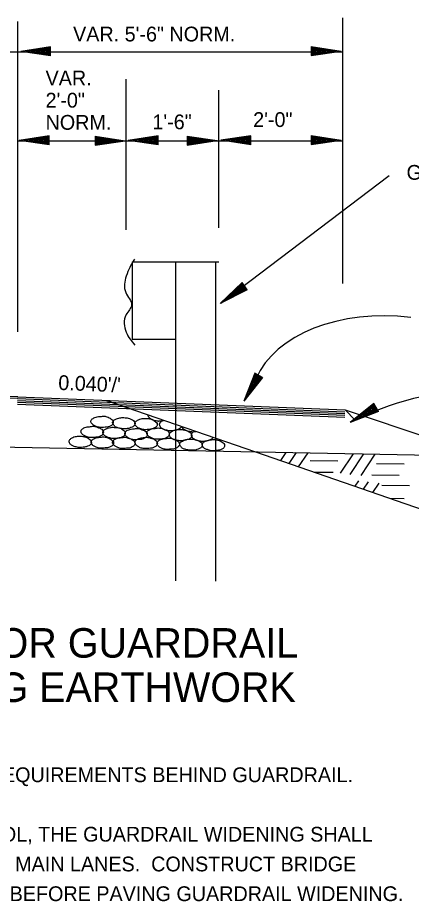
# Model space of a CAD drawing. Extents: x 1929624 to 1936506, y 596315 to 605721.
# Drawn here: x 1934004.9 to 1934166.9, y 603935.3 to 604298.6 of the extents above; entities that cross this region are included whole.
import ezdxf

# ---------------------------------------------------------------- set-up
doc = ezdxf.new("R2010")
doc.units = 0
doc.layers.add('Default', color=7, linetype='Continuous')
doc.layers.add('R_Border', color=7, linetype='Continuous')

msp = doc.modelspace()

# ---------------------------------------------------------------- linework, layer by layer
at = {"layer": 'Default'}
for p, q in [((1934138.62, 604189.31), (1934138.62, 604298.55)), ((1934004.92, 604169.42), (1934004.92, 604296.97)), ((1934018.45, 604286.54), (1934006.13, 604284.69)), ((1934018.45, 604286.22), (1934008.19, 604284.69)), ((1934018.45, 604282.82), (1934018.45, 604286.54)), ((1934125.68, 604286.66), (1934138, 604284.79)), ((1934125.68, 604286.66), (1934125.68, 604282.94)), ((1934125.68, 604286.34), (1934135.94, 604284.79)), ((1933808.09, 604284.47), (1934138.62, 604284.47)), ((1934018.45, 604282.82), (1934006.13, 604284.69)), ((1934018.45, 604283.14), (1934008.19, 604284.69)), ((1934018.45, 604285.9), (1934010.31, 604284.69)), ((1934018.45, 604283.46), (1934010.31, 604284.69)), ((1934018.45, 604285.6), (1934012.38, 604284.69)), ((1934018.45, 604283.76), (1934012.38, 604284.69)), ((1934018.45, 604285.28), (1934014.44, 604284.69)), ((1934018.45, 604284.07), (1934014.44, 604284.69)), ((1934018.45, 604284.96), (1934016.51, 604284.69)), ((1934018.45, 604284.39), (1934016.51, 604284.69)), ((1934125.68, 604286.02), (1934133.82, 604284.79)), ((1934125.68, 604285.72), (1934131.75, 604284.79)), ((1934125.68, 604285.4), (1934129.69, 604284.79)), ((1934125.68, 604285.08), (1934127.62, 604284.79)), ((1934125.68, 604282.94), (1934138, 604284.79)), ((1934125.68, 604284.2), (1934129.69, 604284.79)), ((1934125.68, 604283.58), (1934133.82, 604284.79)), ((1934125.68, 604283.26), (1934135.94, 604284.79)), ((1934125.68, 604283.88), (1934131.75, 604284.79)), ((1934125.68, 604284.52), (1934127.62, 604284.79)), ((1934049.48, 604211.4), (1934049.48, 604273.27)), ((1934087.69, 604212.21), (1934087.69, 604268.77)), ((1934017.79, 604249.97), (1934005.46, 604248.13)), ((1934017.79, 604246.26), (1934017.79, 604249.97)), ((1934036.81, 604249.85), (1934049.14, 604247.98)), ((1934036.81, 604249.85), (1934036.81, 604246.14)), ((1934062.69, 604249.97), (1934050.37, 604248.13)), ((1934062.69, 604246.26), (1934062.69, 604249.97)), ((1934074.67, 604249.88), (1934087, 604248.01)), ((1934074.67, 604249.88), (1934074.67, 604246.16)), ((1934100.78, 604250), (1934088.45, 604248.15)), ((1934100.78, 604246.28), (1934100.78, 604250)), ((1934125.68, 604250.07), (1934138, 604248.2)), ((1934125.68, 604250.07), (1934125.68, 604246.36)), ((1934004.92, 604247.91), (1934138.62, 604247.91)), ((1934017.79, 604246.26), (1934005.46, 604248.13)), ((1934017.79, 604249.65), (1934007.53, 604248.13)), ((1934017.79, 604246.58), (1934007.53, 604248.13)), ((1934017.79, 604249.33), (1934009.65, 604248.13)), ((1934017.79, 604246.9), (1934009.65, 604248.13)), ((1934017.79, 604249.04), (1934011.71, 604248.13)), ((1934017.79, 604247.19), (1934011.71, 604248.13)), ((1934017.79, 604248.72), (1934013.78, 604248.13)), ((1934017.79, 604247.51), (1934013.78, 604248.13)), ((1934017.79, 604248.4), (1934015.85, 604248.13)), ((1934017.79, 604247.83), (1934015.85, 604248.13)), ((1934036.81, 604249.53), (1934047.07, 604247.98)), ((1934036.81, 604249.21), (1934044.95, 604247.98)), ((1934036.81, 604248.92), (1934042.89, 604247.98)), ((1934036.81, 604248.6), (1934040.82, 604247.98)), ((1934036.81, 604248.28), (1934038.75, 604247.98)), ((1934036.81, 604246.14), (1934049.14, 604247.98)), ((1934036.81, 604247.39), (1934040.82, 604247.98)), ((1934036.81, 604246.78), (1934044.95, 604247.98)), ((1934036.81, 604246.46), (1934047.07, 604247.98)), ((1934036.81, 604247.07), (1934042.89, 604247.98)), ((1934036.81, 604247.71), (1934038.75, 604247.98)), ((1934062.69, 604246.26), (1934050.37, 604248.13)), ((1934062.69, 604249.65), (1934052.43, 604248.13)), ((1934062.69, 604246.58), (1934052.43, 604248.13)), ((1934062.69, 604249.33), (1934054.55, 604248.13)), ((1934062.69, 604246.9), (1934054.55, 604248.13)), ((1934062.69, 604249.04), (1934056.61, 604248.13)), ((1934062.69, 604247.19), (1934056.61, 604248.13)), ((1934062.69, 604248.72), (1934058.68, 604248.13)), ((1934062.69, 604247.51), (1934058.68, 604248.13)), ((1934062.69, 604248.4), (1934060.75, 604248.13)), ((1934062.69, 604247.83), (1934060.75, 604248.13)), ((1934074.67, 604249.56), (1934084.93, 604248.01)), ((1934074.67, 604249.24), (1934082.82, 604248.01)), ((1934074.67, 604248.94), (1934080.75, 604248.01)), ((1934074.67, 604248.62), (1934078.68, 604248.01)), ((1934074.67, 604248.3), (1934076.62, 604248.01)), ((1934074.67, 604246.16), (1934087, 604248.01)), ((1934074.67, 604247.42), (1934078.68, 604248.01)), ((1934074.67, 604246.8), (1934082.82, 604248.01)), ((1934074.67, 604246.48), (1934084.93, 604248.01)), ((1934074.67, 604247.1), (1934080.75, 604248.01)), ((1934074.67, 604247.74), (1934076.62, 604248.01)), ((1934100.78, 604246.28), (1934088.45, 604248.15)), ((1934100.78, 604249.68), (1934090.52, 604248.15)), ((1934100.78, 604246.6), (1934090.52, 604248.15)), ((1934100.78, 604249.36), (1934092.63, 604248.15)), ((1934100.78, 604246.92), (1934092.63, 604248.15)), ((1934100.78, 604249.06), (1934094.7, 604248.15)), ((1934100.78, 604247.22), (1934094.7, 604248.15)), ((1934100.78, 604248.74), (1934096.77, 604248.15)), ((1934100.78, 604247.54), (1934096.77, 604248.15)), ((1934100.78, 604248.42), (1934098.83, 604248.15)), ((1934100.78, 604247.86), (1934098.83, 604248.15)), ((1934125.68, 604249.75), (1934135.94, 604248.2)), ((1934125.68, 604249.43), (1934133.82, 604248.2)), ((1934125.68, 604249.14), (1934131.75, 604248.2)), ((1934125.68, 604248.82), (1934129.69, 604248.2)), ((1934125.68, 604248.5), (1934127.62, 604248.2)), ((1934125.68, 604246.36), (1934138, 604248.2)), ((1934125.68, 604247.61), (1934129.69, 604248.2)), ((1934125.68, 604247), (1934133.82, 604248.2)), ((1934125.68, 604246.68), (1934135.94, 604248.2)), ((1934125.68, 604247.29), (1934131.75, 604248.2)), ((1934125.68, 604247.93), (1934127.62, 604248.2)), ((1934088.5, 604181.23), (1934157.81, 604233.61)), ((1934052.04, 604198.23), (1934052.04, 604166.4)), ((1934052.04, 604198.23), (1934087.69, 604198.23)), ((1934069.88, 604198.23), (1934069.88, 604067.05)), ((1934086.26, 604198.08), (1934086.26, 604066.92)), ((1934097.24, 604189.65), (1934088.18, 604181.09)), ((1934097.44, 604189.41), (1934089.86, 604182.25)), ((1934097.64, 604189.11), (1934091.66, 604183.52)), ((1934097.76, 604188.86), (1934093.32, 604184.68)), ((1934097.95, 604188.65), (1934095, 604185.86)), ((1934098.12, 604188.37), (1934096.7, 604187.05)), ((1934099.34, 604186.64), (1934097.24, 604189.65)), ((1934099.34, 604186.64), (1934088.18, 604181.09)), ((1934099.19, 604186.87), (1934089.86, 604182.25)), ((1934098.97, 604187.14), (1934091.66, 604183.52)), ((1934098.79, 604187.41), (1934093.32, 604184.68)), ((1934098.6, 604187.68), (1934095, 604185.86)), ((1934098.47, 604187.96), (1934096.7, 604187.05)), ((1934052.04, 604166.4), (1934069.88, 604166.4)), ((1934102.48, 604152.47), (1934097.9, 604140.86)), ((1934102.72, 604152.27), (1934098.93, 604142.65)), ((1934103.02, 604152.12), (1934099.99, 604144.5)), ((1934103.26, 604151.98), (1934101, 604146.24)), ((1934103.56, 604151.83), (1934102.06, 604148.07)), ((1934105.67, 604150.6), (1934102.48, 604152.47)), ((1934004.92, 604142.7), (1933857.3, 604148.61)), ((1934105.67, 604150.6), (1934097.9, 604140.86)), ((1934105.43, 604150.77), (1934098.93, 604142.65)), ((1934105.11, 604150.89), (1934099.99, 604144.5)), ((1934104.86, 604151.07), (1934101, 604146.24)), ((1934104.59, 604151.21), (1934102.06, 604148.07)), ((1934103.85, 604151.66), (1934103.12, 604149.84)), ((1934104.32, 604151.39), (1934103.12, 604149.84)), ((1934004.92, 604141.96), (1933857.3, 604147.87)), ((1934004.86, 604141.23), (1934139.51, 604135.84)), ((1934004.88, 604141.96), (1934139.54, 604136.58)), ((1934004.92, 604142.7), (1934139.58, 604137.31)), ((1934041.45, 604141.24), (1934102.69, 604120.1)), ((1934004.8, 604139.75), (1934139.46, 604134.36)), ((1934004.82, 604140.49), (1934139.48, 604135.1)), ((1934139.58, 604137.31), (1934320.2, 604077.27)), ((1934139.58, 604137.31), (1934143.81, 604133.11)), ((1934151.44, 604139.95), (1934141.69, 604132.17)), ((1934151.61, 604139.65), (1934143.49, 604133.18)), ((1934151.76, 604139.38), (1934145.31, 604134.26)), ((1934152.96, 604137.26), (1934145.31, 604134.26)), ((1934151.91, 604139.13), (1934147.08, 604135.3)), ((1934152.82, 604137.51), (1934147.08, 604135.3)), ((1934152.05, 604138.84), (1934148.88, 604136.33)), ((1934152.67, 604137.78), (1934148.88, 604136.33)), ((1934152.22, 604138.57), (1934150.7, 604137.36)), ((1934152.52, 604138.08), (1934150.7, 604137.36)), ((1934153.31, 604136.72), (1934151.44, 604139.95)), ((1934153.31, 604136.72), (1934141.69, 604132.17)), ((1934153.14, 604136.99), (1934143.49, 604133.18)), ((1933803.65, 604126.05), (1934197.03, 604118.22)), ((1934102.69, 604120.1), (1934226.74, 604077.27))]:
    msp.add_line(p, q, dxfattribs=at)
msp.add_arc((1934197.2, 604023.84), 121.72, 64.8876, 117.1378, dxfattribs=at)
msp.add_ellipse((1934161.79, 604135.44), major_axis=(-60.8, 7.42), ratio=0.655798, start_param=4.712389, end_param=6.093533, dxfattribs=at)
for points in [[(1934052.9, 604199.27), (1934049.55, 604192.35), (1934049.38, 604185.61), (1934051.79, 604180.42), (1934049.55, 604176.48), (1934049.55, 604169.22), (1934053.1, 604163.98)], [(1934039.79, 604134.69), (1934038.16, 604134.59), (1934036.19, 604134), (1934035.16, 604133.07), (1934035.01, 604132.52), (1934035.5, 604131.54), (1934036.1, 604131.1), (1934037.23, 604130.56), (1934038.8, 604130.11), (1934039.64, 604130.11), (1934040.82, 604130.21), (1934042.15, 604130.36), (1934043.18, 604130.75), (1934044.07, 604131.59), (1934044.21, 604132.23), (1934043.92, 604133.11), (1934043.28, 604133.7), (1934042.59, 604134.1), (1934041.51, 604134.54), (1934040.82, 604134.69), (1934039.79, 604134.69)], [(1934048.6, 604134.16), (1934046.98, 604134.07), (1934045.06, 604133.38), (1934044.08, 604132.59), (1934043.93, 604132.05), (1934044.47, 604131.01), (1934044.91, 604130.47), (1934046.09, 604129.98), (1934047.57, 604129.64), (1934048.41, 604129.54), (1934049.64, 604129.59), (1934051.01, 604129.83), (1934052, 604130.28), (1934053.03, 604131.06), (1934053.18, 604131.7), (1934052.88, 604132.59), (1934052.15, 604133.23), (1934051.41, 604133.57), (1934050.32, 604133.92), (1934049.64, 604134.07), (1934048.6, 604134.16)], [(1934057.78, 604133.8), (1934056.16, 604133.75), (1934054.19, 604133.06), (1934053.2, 604132.17), (1934053.06, 604131.58), (1934053.6, 604130.6), (1934054.14, 604130.15), (1934055.22, 604129.66), (1934056.8, 604129.22), (1934057.63, 604129.17), (1934058.81, 604129.27), (1934060.14, 604129.51), (1934061.17, 604129.91), (1934062.16, 604130.7), (1934062.31, 604131.29), (1934062.01, 604132.17), (1934061.27, 604132.76), (1934060.58, 604133.25), (1934059.5, 604133.6), (1934058.81, 604133.75), (1934057.78, 604133.8)], [(1934058.4, 604135.39), (1934058.4, 604135.36), (1934058.4, 604135.29), (1934058.4, 604135.22), (1934058.48, 604134.95), (1934058.59, 604134.69), (1934058.75, 604134.43), (1934058.84, 604134.31), (1934058.94, 604134.19), (1934059.2, 604133.94), (1934059.49, 604133.75), (1934059.75, 604133.6), (1934060.02, 604133.47), (1934060.29, 604133.35), (1934060.57, 604133.25), (1934061.35, 604133.03), (1934062.14, 604132.86), (1934062.56, 604132.79), (1934062.77, 604132.77), (1934062.98, 604132.76), (1934063.57, 604132.79), (1934063.87, 604132.82), (1934064.16, 604132.86), (1934064.68, 604132.94), (1934065.2, 604133.04)], [(1934035.71, 604130.58), (1934033.99, 604130.38), (1934032.07, 604129.89), (1934031.08, 604128.96), (1934030.94, 604128.42), (1934031.43, 604127.38), (1934032.02, 604126.94), (1934033.1, 604126.35), (1934034.68, 604125.95), (1934035.46, 604125.95), (1934036.69, 604126.05), (1934038.07, 604126.15), (1934039.11, 604126.64), (1934039.99, 604127.48), (1934040.14, 604128.12), (1934039.84, 604129.01), (1934039.11, 604129.6), (1934038.42, 604129.89), (1934037.33, 604130.33), (1934036.69, 604130.53), (1934035.71, 604130.58)], [(1934044.64, 604130.16), (1934043.02, 604130.11), (1934041.05, 604129.47), (1934040.06, 604128.54), (1934039.92, 604128), (1934040.46, 604126.96), (1934041, 604126.52), (1934042.08, 604126.03), (1934043.66, 604125.63), (1934044.49, 604125.54), (1934045.67, 604125.63), (1934047, 604125.88), (1934048.04, 604126.27), (1934049.02, 604127.06), (1934049.17, 604127.7), (1934048.87, 604128.59), (1934048.13, 604129.18), (1934047.45, 604129.62), (1934046.36, 604129.97), (1934045.67, 604130.11), (1934044.64, 604130.16)], [(1934065.06, 604133.09), (1934064.76, 604132.97), (1934064.52, 604132.86), (1934064.28, 604132.74), (1934063.98, 604132.55), (1934063.73, 604132.34), (1934063.5, 604132.09), (1934063.4, 604131.95), (1934063.29, 604131.8), (1934063.22, 604131.67), (1934063.16, 604131.53), (1934063.14, 604131.39), (1934063.14, 604131.33), (1934063.15, 604131.26), (1934063.22, 604130.99), (1934063.34, 604130.73), (1934063.49, 604130.47), (1934063.58, 604130.35), (1934063.69, 604130.23), (1934063.94, 604129.98), (1934064.23, 604129.78), (1934064.49, 604129.64), (1934064.76, 604129.51), (1934065.03, 604129.39), (1934065.31, 604129.29), (1934066.09, 604129.07), (1934066.88, 604128.9), (1934067.72, 604128.8), (1934067.87, 604128.8), (1934068.02, 604128.81), (1934068.31, 604128.83), (1934068.9, 604128.9), (1934069.24, 604128.95), (1934069.57, 604129.01), (1934069.9, 604129.07), (1934070.23, 604129.14), (1934070.5, 604129.22), (1934070.76, 604129.31), (1934071.01, 604129.42), (1934071.26, 604129.54), (1934071.54, 604129.68), (1934071.8, 604129.85), (1934072.03, 604130.06), (1934072.14, 604130.19), (1934072.25, 604130.33), (1934072.32, 604130.45), (1934072.36, 604130.57)], [(1934072.31, 604130.59), (1934072.4, 604130.38), (1934072.5, 604130.18), (1934072.64, 604129.99), (1934072.79, 604129.8), (1934073.04, 604129.55), (1934073.33, 604129.36), (1934073.59, 604129.21), (1934073.86, 604129.08), (1934074.13, 604128.97), (1934074.41, 604128.87), (1934075.19, 604128.64), (1934075.99, 604128.47), (1934076.4, 604128.4), (1934076.61, 604128.38), (1934076.82, 604128.37), (1934077.41, 604128.4), (1934078, 604128.47), (1934078.31, 604128.52)], [(1934030.69, 604126.49), (1934029.07, 604126.44), (1934027.1, 604125.75), (1934026.16, 604124.86), (1934026.02, 604124.27), (1934026.51, 604123.29), (1934027.1, 604122.85), (1934028.13, 604122.35), (1934029.76, 604121.91), (1934030.54, 604121.86), (1934031.77, 604121.96), (1934033.1, 604122.21), (1934034.14, 604122.6), (1934035.07, 604123.39), (1934035.22, 604123.98), (1934034.92, 604124.86), (1934034.18, 604125.45), (1934033.5, 604125.95), (1934032.41, 604126.29), (1934031.72, 604126.44), (1934030.69, 604126.49)], [(1934053.74, 604129.66), (1934052.11, 604129.51), (1934050.14, 604128.97), (1934049.11, 604128.04), (1934048.96, 604127.5), (1934049.5, 604126.51), (1934050.05, 604126.07), (1934051.18, 604125.43), (1934052.7, 604125.09), (1934053.54, 604125.09), (1934054.72, 604125.18), (1934056.15, 604125.23), (1934057.13, 604125.73), (1934058.07, 604126.56), (1934058.21, 604127.2), (1934057.92, 604128.09), (1934057.23, 604128.68), (1934056.49, 604129.02), (1934055.46, 604129.37), (1934054.77, 604129.66), (1934053.74, 604129.66)], [(1934062.69, 604129.89), (1934061.07, 604129.69), (1934059.15, 604129.2), (1934058.16, 604128.27), (1934058.02, 604127.73), (1934058.56, 604126.69), (1934059.1, 604126.25), (1934060.18, 604125.66), (1934061.76, 604125.27), (1934062.54, 604125.27), (1934063.77, 604125.36), (1934065.1, 604125.46), (1934066.19, 604125.95), (1934067.12, 604126.79), (1934067.27, 604127.43), (1934066.97, 604128.32), (1934066.23, 604128.91), (1934065.5, 604129.2), (1934064.46, 604129.69), (1934063.73, 604129.84), (1934062.69, 604129.89)], [(1934071.99, 604129.25), (1934070.37, 604129.2), (1934068.4, 604128.56), (1934067.42, 604127.63), (1934067.27, 604127.09), (1934067.81, 604126.05), (1934068.35, 604125.61), (1934069.43, 604125.12), (1934071.01, 604124.72), (1934071.84, 604124.63), (1934073.03, 604124.72), (1934074.35, 604124.97), (1934075.39, 604125.36), (1934076.37, 604126.15), (1934076.52, 604126.79), (1934076.22, 604127.68), (1934075.49, 604128.27), (1934074.8, 604128.71), (1934073.71, 604129.05), (1934073.03, 604129.2), (1934071.99, 604129.25)], [(1934077.89, 604128.66), (1934077.63, 604128.54), (1934077.49, 604128.47), (1934077.36, 604128.41), (1934077.07, 604128.22), (1934076.82, 604128.01), (1934076.59, 604127.76), (1934076.48, 604127.62), (1934076.38, 604127.47), (1934076.3, 604127.34), (1934076.25, 604127.2), (1934076.22, 604127.06), (1934076.22, 604127), (1934076.23, 604126.93), (1934076.3, 604126.66), (1934076.42, 604126.4), (1934076.58, 604126.14), (1934076.67, 604126.02), (1934076.77, 604125.9), (1934077.03, 604125.65), (1934077.31, 604125.45), (1934077.58, 604125.31), (1934077.84, 604125.18), (1934078.12, 604125.06), (1934078.4, 604124.96), (1934079.18, 604124.74), (1934079.97, 604124.57), (1934080.81, 604124.47), (1934080.96, 604124.47), (1934081.1, 604124.48), (1934081.4, 604124.5), (1934081.99, 604124.57), (1934082.32, 604124.62), (1934082.66, 604124.67), (1934082.99, 604124.74), (1934083.32, 604124.81), (1934083.58, 604124.89), (1934083.84, 604124.98), (1934084.1, 604125.09), (1934084.35, 604125.21), (1934084.63, 604125.35), (1934084.88, 604125.52), (1934085.12, 604125.73), (1934085.23, 604125.85), (1934085.28, 604125.92), (1934085.33, 604125.99), (1934085.38, 604126.07)], [(1934039.79, 604126.2), (1934038.17, 604126.05), (1934036.2, 604125.46), (1934035.27, 604124.58), (1934035.12, 604123.99), (1934035.61, 604123), (1934036.1, 604122.56), (1934037.24, 604122.07), (1934038.76, 604121.58), (1934039.6, 604121.58), (1934040.83, 604121.67), (1934042.21, 604121.87), (1934043.19, 604122.22), (1934044.17, 604123.1), (1934044.32, 604123.69), (1934044.03, 604124.58), (1934043.29, 604125.17), (1934042.55, 604125.61), (1934041.52, 604126), (1934040.83, 604126.15), (1934039.79, 604126.2)], [(1934048.64, 604126.07), (1934047.02, 604125.87), (1934045.05, 604125.33), (1934044.07, 604124.45), (1934043.92, 604123.86), (1934044.46, 604122.87), (1934045, 604122.43), (1934046.08, 604121.84), (1934047.61, 604121.44), (1934048.45, 604121.44), (1934049.68, 604121.54), (1934051.01, 604121.64), (1934052.04, 604122.08), (1934053.02, 604122.97), (1934053.17, 604123.56), (1934052.87, 604124.45), (1934052.14, 604125.04), (1934051.4, 604125.38), (1934050.32, 604125.77), (1934049.68, 604126.02), (1934048.64, 604126.07)], [(1934057.9, 604126.08), (1934056.23, 604125.88), (1934054.26, 604125.34), (1934053.28, 604124.45), (1934053.13, 604123.86), (1934053.67, 604122.88), (1934054.21, 604122.44), (1934055.34, 604121.8), (1934056.87, 604121.45), (1934057.66, 604121.45), (1934058.89, 604121.5), (1934060.26, 604121.65), (1934061.3, 604122.09), (1934062.23, 604122.98), (1934062.38, 604123.57), (1934062.08, 604124.45), (1934061.35, 604125.04), (1934060.61, 604125.39), (1934059.58, 604125.73), (1934058.94, 604125.93), (1934057.9, 604126.08)], [(1934066.97, 604125.71), (1934065.25, 604125.51), (1934063.38, 604125.02), (1934062.35, 604124.08), (1934062.2, 604123.54), (1934062.74, 604122.51), (1934063.28, 604122.07), (1934064.41, 604121.48), (1934065.94, 604121.08), (1934066.73, 604121.08), (1934067.96, 604121.18), (1934069.38, 604121.28), (1934070.37, 604121.77), (1934071.3, 604122.61), (1934071.45, 604123.25), (1934071.16, 604124.13), (1934070.42, 604124.72), (1934069.73, 604125.02), (1934068.65, 604125.41), (1934068.01, 604125.66), (1934066.97, 604125.71)], [(1934076.25, 604125.33), (1934074.62, 604125.23), (1934072.71, 604124.54), (1934071.72, 604123.76), (1934071.57, 604123.22), (1934072.12, 604122.18), (1934072.56, 604121.64), (1934073.74, 604121.15), (1934075.22, 604120.8), (1934076.05, 604120.71), (1934077.28, 604120.76), (1934078.66, 604121), (1934079.64, 604121.44), (1934080.68, 604122.23), (1934080.82, 604122.87), (1934080.53, 604123.76), (1934079.79, 604124.4), (1934079.05, 604124.74), (1934077.97, 604125.09), (1934077.28, 604125.23), (1934076.25, 604125.33)], [(1934085.5, 604125.14), (1934083.88, 604125), (1934081.91, 604124.4), (1934080.97, 604123.52), (1934080.82, 604122.93), (1934081.32, 604121.94), (1934081.81, 604121.5), (1934082.94, 604121.01), (1934084.47, 604120.52), (1934085.3, 604120.52), (1934086.53, 604120.62), (1934087.91, 604120.81), (1934088.89, 604121.16), (1934089.88, 604122.04), (1934090.03, 604122.63), (1934089.73, 604123.52), (1934088.99, 604124.11), (1934088.26, 604124.55), (1934087.22, 604124.95), (1934086.53, 604125.09), (1934085.5, 604125.14)]]:
    msp.add_spline(points, degree=3, dxfattribs=at)
at = {"layer": 'R_Border'}
for p, q in [((1934113.15, 604116.49), (1934115.42, 604119.84)), ((1934116.64, 604115.28), (1934119.66, 604119.76)), ((1934120.5, 604113.95), (1934124.36, 604119.67)), ((1934137.73, 604111.31), (1934143.11, 604119.29)), ((1934141.71, 604110.84), (1934147.36, 604119.21)), ((1934146.16, 604110.38), (1934152.05, 604119.12)), ((1934125.3, 604116.5), (1934136.61, 604116.41)), ((1934152.56, 604115.3), (1934163.87, 604115.2)), ((1934126.89, 604111.74), (1934134.67, 604111.68)), ((1934143.72, 604105.93), (1934145.23, 604108.18)), ((1934150.61, 604110.57), (1934161.92, 604110.47)), ((1934147.21, 604104.73), (1934149.22, 604107.71)), ((1934151.07, 604103.39), (1934153.67, 604107.25)), ((1934154.78, 604106.41), (1934166.09, 604106.32)), ((1934158.03, 604100.99), (1934163.87, 604100.94))]:
    msp.add_line(p, q, dxfattribs=at)

# ---------------------------------------------------------------- texts
at = {"layer": 'Default'}
for s, height, rotation, p in [('VAR. 5\'-6" NORM.', 6.075, 360, (1934027.69, 604288.78)), ('VAR.', 6.075, 360, (1934016.36, 604270.7)), ('2\'-0"', 6.075, 360, (1934016.36, 604261.59)), ('NORM.', 6.075, 360, (1934016.36, 604252.48)), ('1\'-6"', 6.075, 360, (1934060.33, 604252.68)), ('2\'-0"', 6.075, 360, (1934101.79, 604253.62)), ('GUARDRAIL (TYPE A)', 6.075, 360, (1934164.9, 604231.92)), ("0.040'/'", 6.075, 357.7094, (1934021.5, 604145.57)), ('WIDENING FOR GUARDRAIL', 12.15, 360, (1933899.15, 604035.48)), ('REQUIRING EARTHWORK', 12.15, 360, (1933917.15, 604017.26)), ('   1.  REFER TO STD. DWG. GR-9 FOR SLOPE REQUIREMENTS BEHIND GUARDRAIL.', 6.075, 360, (1933815.62, 603984.32)), ('   2.  FOR HORIZONTAL AND VERTICAL CONTROL, THE GUARDRAIL WIDENING SHALL', 6.075, 360, (1933815.62, 603959.87)), ('       MATCH THE SLOPES AND GRADES OF THE MAIN LANES.  CONSTRUCT BRIDGE ', 6.075, 360, (1933815.62, 603947.64)), ('       APPROACH AND MAIN LANE TRANSITIONS BEFORE PAVING GUARDRAIL WIDENING.', 6.075, 360, (1933815.62, 603935.42))]:
    msp.add_text(s, height=height, rotation=rotation, dxfattribs=at).set_placement(p)

doc.saveas('drawing.dxf')
